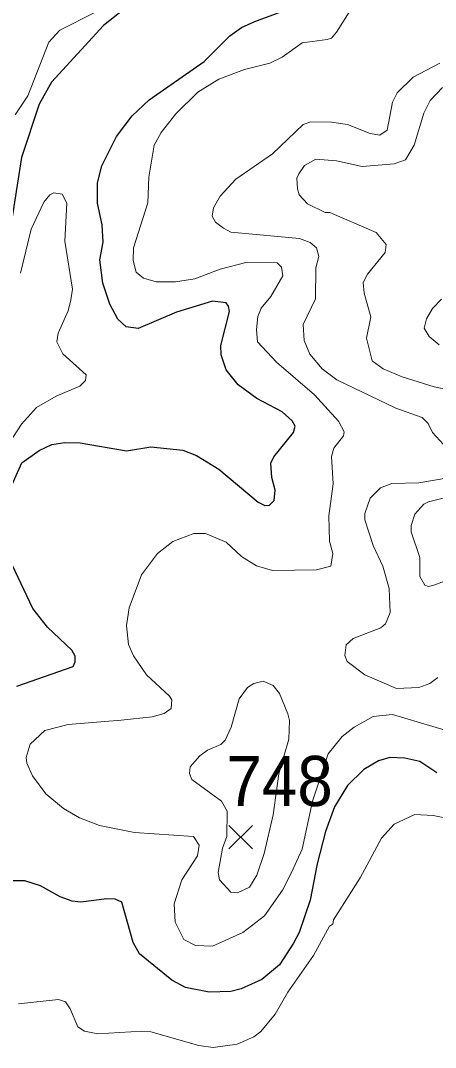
# Model space of a CAD drawing. Extents: x 294.2 to 320.3, y 7482.7 to 7510.7.
# Drawn here: x 313.766 to 314.427, y 7495.42 to 7497.059 of the extents above; entities that cross this region are included whole.
import ezdxf
from ezdxf.enums import TextEntityAlignment as Align

# ---------------------------------------------------------------- set-up
doc = ezdxf.new("R2010")
doc.units = 0
doc.header["$LTSCALE"] = 0.032
for name, color, linetype, lineweight in [('1', 7, 'Continuous', 25), ('2', 7, 'Continuous', 13), ('21', 7, 'Continuous', 25)]:
    doc.layers.add(name, color=color, linetype=linetype, lineweight=lineweight)
doc.layers.add('61', color=7, linetype='Continuous')

msp = doc.modelspace()

# ---------------------------------------------------------------- linework, layer by layer
at = {"layer": '1'}
for points in [[(313.9538, 7497.0959), (313.8979, 7497.0511), (313.8147, 7496.9609), (313.795, 7496.9255), (313.7671, 7496.8406), (313.7439, 7496.6912)], [(314.1549, 7496.2852), (314.1628, 7496.286), (314.1698, 7496.2931), (314.1718, 7496.3096), (314.1663, 7496.3301), (314.1648, 7496.3529), (314.1695, 7496.3631), (314.2009, 7496.4016), (314.2033, 7496.4119), (314.1986, 7496.4205), (314.1828, 7496.4347), (314.1422, 7496.4559), (314.1128, 7496.4776), (314.0937, 7496.5019), (314.0854, 7496.5256), (314.0847, 7496.5404), (314.0989, 7496.5947), (314.0973, 7496.6033), (314.0934, 7496.6088), (314.0714, 7496.6112), (314.0142, 7496.5939), (313.9529, 7496.568), (313.934, 7496.5703), (313.9207, 7496.5829), (313.9077, 7496.6065), (313.8967, 7496.6403), (313.892, 7496.6773), (313.8975, 7496.7056), (313.8959, 7496.7331), (313.8883, 7496.7677), (313.8883, 7496.8003), (313.8954, 7496.8275), (313.9186, 7496.8739), (313.9438, 7496.9069), (313.9705, 7496.9329), (314.0582, 7496.994), (314.0991, 7497.0349), (314.1179, 7497.0483), (314.1394, 7497.0577), (314.2152, 7497.0859)], [(313.7472, 7496.308), (313.7677, 7496.3536), (313.7952, 7496.3733), (313.8156, 7496.3827), (313.8361, 7496.3859), (313.8607, 7496.3851), (313.9347, 7496.3723)], [(313.9347, 7496.3723), (313.9731, 7496.3787), (314.0241, 7496.3736), (314.0464, 7496.3653), (314.0818, 7496.3434), (314.1447, 7496.2907), (314.1549, 7496.2852)], [(313.7595, 7495.9972), (313.8494, 7496.0286), (313.8526, 7496.0357), (313.8526, 7496.0451), (313.8471, 7496.0546), (313.8086, 7496.091), (313.785, 7496.1209), (313.7523, 7496.1908)], [(314.4294, 7495.8587), (314.4021, 7495.8768), (314.3783, 7495.8823), (314.3547, 7495.8831), (314.3366, 7495.8776), (314.313, 7495.8642), (314.2872, 7495.8384), (314.266, 7495.8046), (314.2518, 7495.7653), (314.2387, 7495.7134), (314.2272, 7495.6553), (314.2099, 7495.6036), (314.2009, 7495.587), (314.1786, 7495.5525), (314.1505, 7495.5289), (314.1173, 7495.5142), (314.1007, 7495.5097), (314.0663, 7495.5084), (314.0286, 7495.5161), (314.0069, 7495.5276), (313.9554, 7495.5697), (313.9452, 7495.5878), (313.9271, 7495.6523), (313.9165, 7495.657), (313.9032, 7495.6578), (313.8615, 7495.6523), (313.8481, 7495.6538), (313.8285, 7495.6609), (313.7974, 7495.6782), (313.7722, 7495.6861), (313.747, 7495.6861)]]:
    msp.add_lwpolyline(points, dxfattribs=at)
at = {"layer": '2'}
for points in [[(313.8849, 7497.0727), (313.8281, 7497.044), (313.8108, 7497.0248), (313.777, 7496.9393), (313.7572, 7496.9087)], [(313.8913, 7495.7747), (313.8594, 7495.7869), (313.8338, 7495.8015), (313.8057, 7495.8252), (313.7847, 7495.8539), (313.7758, 7495.8743), (313.7745, 7495.8833), (313.7809, 7495.9043), (313.8044, 7495.926), (313.8415, 7495.9356), (313.9258, 7495.9426), (313.9756, 7495.9478), (313.9948, 7495.9535), (314.0056, 7495.9611), (314.0069, 7495.9752), (314.003, 7495.9809), (313.9666, 7496.0148), (313.9456, 7496.0454), (313.9379, 7496.0633), (313.9347, 7496.094), (313.9385, 7496.1221), (313.9583, 7496.1744), (313.9839, 7496.2089), (314.0082, 7496.228), (314.042, 7496.2408), (314.0605, 7496.2408), (314.0937, 7496.2267), (314.1179, 7496.2038), (314.1416, 7496.1891), (314.1672, 7496.1814), (314.2374, 7496.1827), (314.2603, 7496.1884), (314.2636, 7496.2089), (314.2584, 7496.2281), (314.2572, 7496.2689), (314.2642, 7496.32), (314.2616, 7496.3634), (314.2654, 7496.3768), (314.2808, 7496.3966), (314.2814, 7496.403), (314.2725, 7496.4196), (314.2342, 7496.4617), (314.1735, 7496.5141), (314.1435, 7496.5466), (314.1416, 7496.5664), (314.1441, 7496.5869), (314.1492, 7496.6002), (314.1646, 7496.6188), (314.1837, 7496.652), (314.1818, 7496.6654), (314.1748, 7496.6724), (314.125, 7496.6731), (314.0841, 7496.6622), (314.0433, 7496.6468), (314.0126, 7496.6424), (313.982, 7496.6424), (313.9616, 7496.6481), (313.95, 7496.6577), (313.9449, 7496.6763), (313.9456, 7496.6967), (313.9686, 7496.7682), (313.9699, 7496.8091), (313.9788, 7496.8601), (313.9896, 7496.8806), (314.0133, 7496.9105), (314.0483, 7496.945), (314.0816, 7496.9655), (314.1225, 7496.9808), (314.1633, 7496.991), (314.1825, 7497.0006), (314.2144, 7497.0236), (314.2546, 7497.0287), (314.2616, 7497.0312), (314.2693, 7497.0408), (314.2935, 7497.0785)], [(314.4576, 7496.3634), (314.4225, 7496.4017), (314.4155, 7496.4164), (314.4059, 7496.4259), (314.3638, 7496.4407), (314.2699, 7496.486), (314.2463, 7496.5032), (314.2271, 7496.5269), (314.2176, 7496.5485), (314.2163, 7496.5741), (314.2361, 7496.615), (314.2367, 7496.6648), (314.2412, 7496.6826), (314.2374, 7496.6966), (314.2272, 7496.705), (314.2106, 7496.7114), (314.1007, 7496.7216), (314.0893, 7496.728), (314.0764, 7496.7375), (314.0713, 7496.7471), (314.0733, 7496.7605), (314.0841, 7496.779), (314.109, 7496.8059), (314.1671, 7496.8467), (314.2163, 7496.8933), (314.2284, 7496.8978), (314.2616, 7496.8971), (314.2872, 7496.8933), (314.3229, 7496.8787), (314.3383, 7496.8761), (314.3504, 7496.8844), (314.3586, 7496.9291), (314.3663, 7496.9438), (314.3919, 7496.9687), (314.434, 7496.991)], [(314.4762, 7496.4642), (314.4251, 7496.4745), (314.374, 7496.4905), (314.344, 7496.5032), (314.3261, 7496.516), (314.3172, 7496.5524), (314.3242, 7496.5862), (314.3134, 7496.6239), (314.3121, 7496.6411), (314.3191, 7496.6546), (314.3472, 7496.689), (314.3484, 7496.7018), (314.3325, 7496.7209), (314.259, 7496.7528), (314.2514, 7496.7528), (314.2233, 7496.7669), (314.2099, 7496.7809), (314.2074, 7496.7905), (314.2061, 7496.8078), (314.2093, 7496.8148), (314.2182, 7496.8276), (314.2367, 7496.8378), (314.2693, 7496.8352), (314.3102, 7496.8263), (314.3612, 7496.8307), (314.3797, 7496.8371), (314.3931, 7496.8601), (314.4085, 7496.9112), (314.4187, 7496.9317), (314.4385, 7496.9521)], [(313.7655, 7496.6558), (313.7827, 7496.7261), (313.8026, 7496.7695), (313.8121, 7496.7809), (313.8185, 7496.7842), (313.8319, 7496.7822), (313.8396, 7496.7675), (313.8364, 7496.7069), (313.8485, 7496.6303), (313.846, 7496.6137), (313.8415, 7496.5958), (313.8256, 7496.5601), (313.8236, 7496.5466), (313.8332, 7496.5275), (313.8703, 7496.4937), (313.869, 7496.4847), (313.86, 7496.4758), (313.8224, 7496.4598), (313.791, 7496.4419), (313.7668, 7496.4151), (313.7483, 7496.3864)], [(314.4334, 7496.5415), (314.4174, 7496.5549), (314.4091, 7496.5683), (314.4129, 7496.583), (314.4225, 7496.5996), (314.4366, 7496.6143)], [(314.4308, 7496.0109), (314.4181, 7496.0014), (314.4008, 7495.995), (314.3651, 7495.9931), (314.3146, 7496.0148), (314.2865, 7496.0365), (314.2827, 7496.046), (314.2846, 7496.0627), (314.2961, 7496.0729), (314.3401, 7496.0901), (314.3478, 7496.0965), (314.3548, 7496.1144), (314.3536, 7496.1527), (314.3433, 7496.1885), (314.328, 7496.2217), (314.3146, 7496.2625), (314.3146, 7496.2727), (314.3229, 7496.297), (314.3395, 7496.3136), (314.3574, 7496.3206), (314.4008, 7496.3212), (314.4474, 7496.3296)], [(314.457, 7496.1705), (314.4264, 7496.1585), (314.4162, 7496.1559), (314.4104, 7496.1584), (314.4021, 7496.1718), (314.4021, 7496.2025), (314.3887, 7496.2434), (314.3887, 7496.2536), (314.3944, 7496.2715), (314.4085, 7496.2874), (314.4162, 7496.2913), (314.4672, 7496.304)], [(314.4876, 7495.9133), (314.3587, 7495.9516), (314.328, 7495.9484), (314.2974, 7495.9318), (314.2782, 7495.9164), (314.2559, 7495.889), (314.2313, 7495.8135), (314.2146, 7495.7369), (314.1978, 7495.6994), (314.1831, 7495.6713), (314.1544, 7495.6304), (314.1199, 7495.6036), (314.0714, 7495.5819), (314.0446, 7495.5831), (314.026, 7495.5928), (314.012, 7495.6202), (314.0107, 7495.6496)], [(313.7624, 7495.4899), (313.8262, 7495.497), (313.837, 7495.4931), (313.8447, 7495.4823), (313.8568, 7495.4535), (313.8677, 7495.4465), (313.8888, 7495.4421), (313.959, 7495.4465), (313.9731, 7495.4452), (314.0497, 7495.4235), (314.0727, 7495.4204), (314.111, 7495.4255), (314.1378, 7495.4376), (314.1486, 7495.4459), (314.1716, 7495.4734), (314.192, 7495.5085), (314.2329, 7495.5672), (314.2584, 7495.6138), (314.2636, 7495.617), (314.2648, 7495.6241), (314.307, 7495.6911), (314.3414, 7495.7543), (314.3612, 7495.7766), (314.3944, 7495.792), (314.4238, 7495.7907), (314.48, 7495.7792)], [(314.0107, 7495.6496), (314.0228, 7495.6879), (314.0477, 7495.7262), (314.0503, 7495.7434), (314.0414, 7495.7568), (313.9475, 7495.7632), (313.8913, 7495.7747)]]:
    msp.add_lwpolyline(points, dxfattribs=at)
msp.add_lwpolyline([(314.192, 7495.9528), (314.1946, 7495.942), (314.1933, 7495.9126), (314.1774, 7495.8571), (314.1685, 7495.7918), (314.1543, 7495.73), (314.1422, 7495.6956), (314.1307, 7495.6764), (314.1116, 7495.6674), (314.1007, 7495.6681), (314.0828, 7495.6879), (314.0809, 7495.6994), (314.0875, 7495.7384), (314.0945, 7495.7573), (314.0953, 7495.7974), (314.086, 7495.8137), (314.0388, 7495.8481), (314.035, 7495.8577), (314.0363, 7495.868), (314.0516, 7495.8858), (314.0637, 7495.8947), (314.0848, 7495.9037), (314.0918, 7495.9107), (314.1014, 7495.9318), (314.1141, 7495.9765), (314.1276, 7495.995), (314.1378, 7496.0014), (314.1524, 7496.0052), (314.1684, 7495.9982), (314.1786, 7495.9854)], close=True, dxfattribs=at)
at = {"layer": '21'}
for p, q in [((314.0977, 7495.7748), (314.1352, 7495.7373)), ((314.1352, 7495.7748), (314.0977, 7495.7373))]:
    msp.add_line(p, q, dxfattribs=at)

# ---------------------------------------------------------------- texts
at = {"layer": '61', "width": 0.95}
msp.add_text('748', height=0.08, dxfattribs=at).set_placement((314.1787, 7495.8057), align=Align.CENTER)

doc.saveas('drawing.dxf')
